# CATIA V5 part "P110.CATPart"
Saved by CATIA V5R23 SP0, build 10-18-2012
Part number: P110
Definition: Plateau
Bounding box of the stored display mesh (mm): x -73.977 to 73.977, y -73.995 to 73.995, z 0 to 18
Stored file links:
  C:\wamp\www\COURS\CONCEPTION GMP1\TITRE 02-SEMESTRE 2\03-TP7-PRESSE MECANIQUE\eleve\P110.CATPart
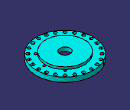
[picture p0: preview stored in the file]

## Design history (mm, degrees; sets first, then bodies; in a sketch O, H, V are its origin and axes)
Body1 (main body)
  Sketch1 on yz-plane, origin (0, 0, 0), H (0, 1, 0), V (0, 0, 1)
    point P1 (-74, 0)
    line L1 (-74, 0) -> (-40, 0)
    line L2 (-40, 0) -> (-40, 8)
    line L3 (-40, 8) -> (0, 8)
    point P4 (0, 8)
    line L4 (-74, 0) -> (-74, 12)
    line L5 (-74, 12) -> (-50, 12)
    line L6 (-50, 12) -> (-50, 18)
    line L7 (-50, 18) -> (0, 18)
    point P8 (0, 18)
    length L1 = 34
    length L7 = 50
    length L5 = 24
    distance L5 L1 = 12
    distance L3 L7 = 10
    distance L3 H = 8
    coincidence: P1 H, P4 V, P8 V
    horizontal: L1 H, L3 H, L5 H, L7 H
    vertical: L2 V, L4 V, L6 V
  Shaft1: profile Sketch1, axis Sketch1.V, angle 360
  Sketch2 on face of Shaft1, origin (-9.5267, 64.3701, 12), H (1, 0, 0), V (0, 1, 0)
    point P1 (9.5267, 3.6299)
    reference intersected line E1 through (9.5267, 0) direction (0, 1) from yz-plane
    reference intersected line E2 through (0, -64.3701) direction (-1, 0) from zx-plane
    distance P1 E2 = 68
    coincidence: P1 E1
  Hole1: placed by Sketch2, at (0, 68, 12) direction (0, 0, -1), diameter 8, through (limit type 3)
  CircPattern1: of Hole1, instances 25, angular step 15, axis from face of Shaft1
  Sketch3 on face of Shaft1, origin (0, 0, 18), H (1, 0, 0), V (0, 1, 0)
    point P1 (0, 0)
  Hole2: placed by Sketch3, at (0, 0, 18) direction (0, 0, -1), diameter 26, through (limit type 3)
  Hole3: placed by Sketch4, at (54, 0, 12) direction (0, 0, -1), diameter 6, through (limit type 3)
  Sketch4 on face of Shaft1, origin (3.7825, -57.6423, 12), H (1, 0, 0), V (0, 1, 0)
    point P1 (50.2175, 57.6423)
    construction circle A1 centre (-3.7825, 57.6423) radius 54
    point P2 (-3.7825, 57.6423)
    reference intersected line E1 through (0, 57.6423) direction (-1, 0) from zx-plane
    reference intersected line E2 through (-3.7825, 0) direction (0, 1) from yz-plane
    reference intersected line E3 through (0, 57.6423) direction (-1, 0) from zx-plane
    point P3 (34.4013, 95.8261)
    construction line L1 (-83.129, 57.6423) -> (86.8768, 57.6423)
    construction line L2 (61.892, 123.3168) -> (-25.4923, 35.9324)
    construction line L3 (60.2778, -6.4179) -> (-20.3588, 74.2186)
    point P10 (34.4013, 19.4585)
    point P11 (-57.7825, 57.6423)
    radius A1 = 54
    angle L2 L1 = 45
    angle L3 L1 = 45
    coincidence: P2 E1, E2 P2, P1 A1, P1 E3, P3 A1, L2 P2, P3 L2, L3 P2, P10 A1, L3 P10, L1 P2, P11 A1, P11 L1
    horizontal: L1 H
  UserPattern1: of Hole3, copies 4, at the points of Sketch4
